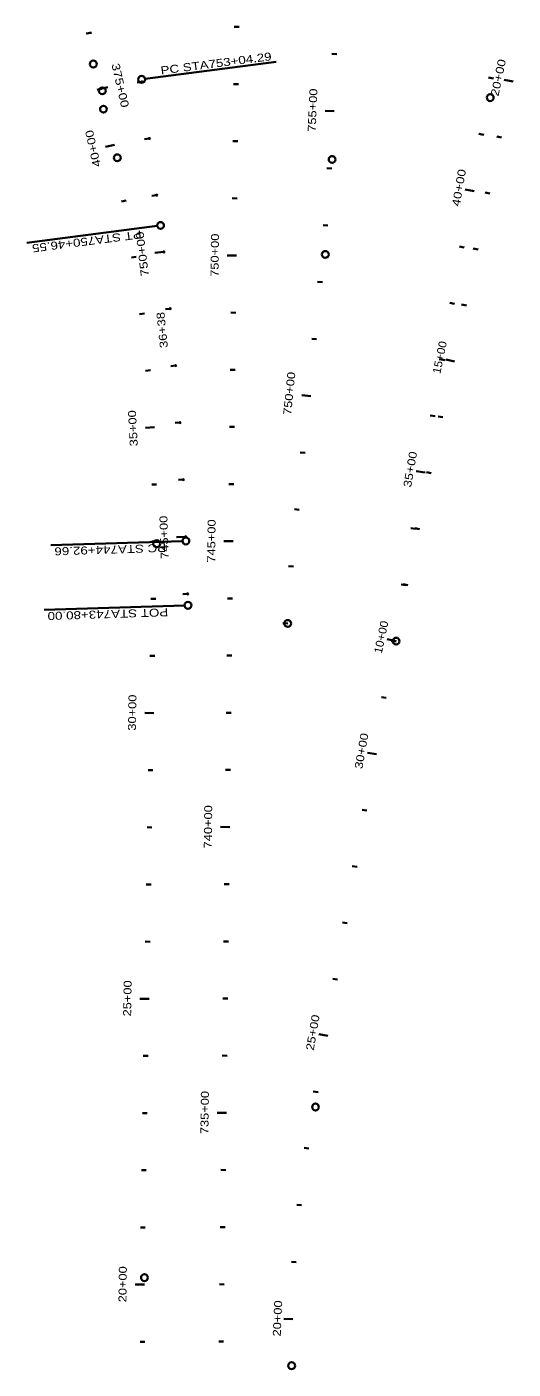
# Model space of a CAD drawing. Extents: x 2357892 to 2370172, y 6966790 to 6985499.
# Drawn here: x 2364100 to 2364952, y 6973878 to 6976226 of the extents above; entities that cross this region are included whole.
import ezdxf
from ezdxf.enums import TextEntityAlignment as Align

# ---------------------------------------------------------------- set-up
doc = ezdxf.new("R2010")
doc.units = 0
doc.header["$LTSCALE"] = 5.6
doc.header["$PDMODE"] = 32
doc.header["$PDSIZE"] = 2.8
doc.layers.add('28', color=7, linetype='Continuous', lineweight=35)
doc.layers.add('7', color=7, linetype='Continuous')

msp = doc.modelspace()

# ---------------------------------------------------------------- linework, layer by layer
at = {"layer": '28'}
for p, q in [((2364212.49, 6976215.881), (2364204.101, 6976214.51)), ((2364205.021, 6976214.781), (2364213.364, 6976216.407)), ((2364471.937, 6976226.218), (2364463.438, 6976226.319)), ((2364307.078, 6976135.201), (2364536.71, 6976164.913)), ((2364642.877, 6976178.521), (2364634.385, 6976178.891)), ((2364917.253, 6976136.182), (2364908.853, 6976137.484)), ((2364231.417, 6976117.689), (2364223.12, 6976115.844)), ((2364226.357, 6976117.089), (2364241.959, 6976120.636)), ((2364301.678, 6976130.177), (2364293.248, 6976129.087)), ((2364470.757, 6976126.225), (2364462.257, 6976126.326)), ((2364952.037, 6976130.422), (2364936.377, 6976133.703)), ((2364638.533, 6976078.616), (2364622.548, 6976079.311)), ((2364253.306, 6976020.114), (2364237.694, 6976016.611)), ((2364314.51, 6976031.004), (2364306.08, 6976029.913)), ((2364469.576, 6976026.232), (2364461.077, 6976026.333)), ((2364900.478, 6976037.601), (2364892.103, 6976039.052)), ((2364931.529, 6976032.548), (2364923.21, 6976034.291)), ((2364634.146, 6975978.712), (2364625.656, 6975979.128)), ((2364327.342, 6975931.831), (2364318.912, 6975930.74)), ((2364468.396, 6975926.239), (2364459.897, 6975926.34)), ((2364883.404, 6975939.069), (2364867.639, 6975941.801)), ((2364911.021, 6975934.673), (2364902.702, 6975936.416)), ((2364274.199, 6975922.32), (2364265.858, 6975920.682)), ((2364627.516, 6975878.937), (2364619.046, 6975879.649)), ((2364328.25, 6975878.048), (2364099.932, 6975848.506)), ((2364339.986, 6975832.634), (2364324.102, 6975830.71)), ((2364866.329, 6975840.538), (2364857.954, 6975841.989)), ((2364890.513, 6975836.799), (2364882.194, 6975838.542)), ((2364291.759, 6975823.874), (2364283.367, 6975822.528)), ((2364467.216, 6975826.246), (2364451.217, 6975826.435)), ((2364617.823, 6975779.41), (2364609.367, 6975780.272)), ((2364849.255, 6975742.006), (2364840.879, 6975743.457)), ((2364870.005, 6975738.924), (2364861.686, 6975740.667)), ((2364305.873, 6975724.875), (2364297.439, 6975723.823)), ((2364351.145, 6975733.26), (2364342.69, 6975732.385)), ((2364466.035, 6975726.253), (2364457.536, 6975726.354)), ((2364607.679, 6975679.926), (2364599.223, 6975680.788)), ((2364832.18, 6975643.475), (2364823.805, 6975644.926)), ((2364849.497, 6975641.05), (2364833.837, 6975644.331)), ((2364316.524, 6975625.444), (2364308.058, 6975624.687)), ((2364360.568, 6975633.706), (2364352.099, 6975632.979)), ((2364464.855, 6975626.26), (2364456.356, 6975626.361)), ((2364597.534, 6975580.441), (2364581.617, 6975582.065)), ((2364368.252, 6975534.003), (2364359.772, 6975533.424)), ((2364463.675, 6975526.267), (2364455.175, 6975526.368)), ((2364815.105, 6975544.943), (2364806.73, 6975546.394)), ((2364828.989, 6975543.175), (2364820.67, 6975544.918)), ((2364323.697, 6975525.702), (2364307.721, 6975524.833)), ((2364587.39, 6975480.957), (2364578.934, 6975481.82)), ((2364374.195, 6975434.181), (2364365.706, 6975433.75)), ((2364798.031, 6975446.412), (2364782.266, 6975449.144)), ((2364808.481, 6975445.301), (2364800.162, 6975447.044)), ((2364327.385, 6975425.77), (2364318.887, 6975425.605)), ((2364462.494, 6975426.274), (2364453.995, 6975426.374)), ((2364577.245, 6975381.473), (2364568.789, 6975382.336)), ((2364780.956, 6975347.88), (2364772.581, 6975349.331)), ((2364787.973, 6975347.426), (2364779.654, 6975349.169)), ((2364372.637, 6975326.745), (2364141.762, 6975319.354)), ((2364327.583, 6975325.77), (2364319.084, 6975325.902)), ((2364378.395, 6975334.27), (2364362.403, 6975333.738)), ((2364461.314, 6975326.281), (2364445.315, 6975326.47)), ((2364567.101, 6975281.989), (2364558.644, 6975282.851)), ((2364763.882, 6975249.349), (2364755.506, 6975250.8)), ((2364767.465, 6975249.552), (2364759.146, 6975251.295)), ((2364325.91, 6975225.784), (2364317.411, 6975225.927)), ((2364381.599, 6975234.322), (2364373.103, 6975234.05)), ((2364460.134, 6975226.288), (2364451.634, 6975226.388)), ((2364376.242, 6975214.14), (2364130.382, 6975206.269)), ((2364556.956, 6975182.505), (2364548.5, 6975183.367)), ((2364746.957, 6975151.677), (2364731.297, 6975154.958)), ((2364746.807, 6975150.817), (2364738.432, 6975152.268)), ((2364324.234, 6975125.798), (2364315.735, 6975125.941)), ((2364458.953, 6975126.295), (2364450.454, 6975126.395)), ((2364729.732, 6975052.286), (2364721.357, 6975053.737)), ((2364322.557, 6975025.812), (2364306.56, 6975026.08)), ((2364457.773, 6975026.302), (2364449.274, 6975026.402)), ((2364712.658, 6974953.754), (2364696.893, 6974956.486)), ((2364320.881, 6974925.826), (2364312.382, 6974925.969)), ((2364456.593, 6974926.309), (2364448.093, 6974926.409)), ((2364695.583, 6974855.223), (2364687.208, 6974856.674)), ((2364319.205, 6974825.84), (2364310.706, 6974825.983)), ((2364455.412, 6974826.316), (2364439.414, 6974826.505)), ((2364678.509, 6974756.691), (2364670.133, 6974758.142)), ((2364317.529, 6974725.854), (2364309.03, 6974725.997)), ((2364454.232, 6974726.323), (2364445.733, 6974726.423)), ((2364661.434, 6974658.16), (2364653.059, 6974659.611)), ((2364315.853, 6974625.868), (2364307.354, 6974626.011)), ((2364453.052, 6974626.33), (2364444.552, 6974626.43)), ((2364644.359, 6974559.628), (2364635.984, 6974561.079)), ((2364314.177, 6974525.882), (2364298.179, 6974526.151)), ((2364451.872, 6974526.337), (2364443.372, 6974526.437)), ((2364627.285, 6974461.097), (2364611.52, 6974463.828)), ((2364312.501, 6974425.896), (2364304.002, 6974426.039)), ((2364450.691, 6974426.344), (2364442.192, 6974426.444)), ((2364610.21, 6974362.565), (2364601.835, 6974364.016)), ((2364310.824, 6974325.91), (2364302.326, 6974326.053)), ((2364449.511, 6974326.351), (2364433.512, 6974326.54)), ((2364594.067, 6974263.88), (2364585.657, 6974265.116)), ((2364309.148, 6974225.925), (2364300.649, 6974226.067)), ((2364448.331, 6974226.358), (2364439.831, 6974226.458)), ((2364581.256, 6974164.709), (2364572.809, 6974165.651)), ((2364307.472, 6974125.939), (2364298.973, 6974126.081)), ((2364447.15, 6974126.365), (2364438.651, 6974126.465)), ((2364571.915, 6974065.152), (2364563.439, 6974065.798)), ((2364305.829, 6974025.949), (2364289.83, 6974026.131)), ((2364445.97, 6974026.372), (2364437.47, 6974026.472)), ((2364566.053, 6973965.329), (2364550.067, 6973965.988)), ((2364306.868, 6973925.954), (2364298.373, 6973925.68)), ((2364444.79, 6973926.379), (2364436.29, 6973926.479))]:
    msp.add_line(p, q, dxfattribs=at)
for centre in [(2364216.334, 6976161.176), (2364301.127, 6976134.431), (2364232.156, 6976114.382), (2364911.733, 6976102.547), (2364234.264, 6976082.306), (2364258.432, 6975997.267), (2364634.866, 6975994.298), (2364334.201, 6975878.818), (2364622.792, 6975828.132), (2364327.524, 6975322.079), (2364378.634, 6975326.937), (2364382.239, 6975214.332), (2364556.956, 6975182.505), (2364746.957, 6975151.677), (2364605.692, 6974336.49), (2364306.001, 6974038.189), (2364563.857, 6973883.997)]:
    msp.add_circle(centre, 6, dxfattribs=at)
at = {"layer": '7'}
for p in [(2364301.678, 6976130.177), (2364314.51, 6976031.004), (2364327.342, 6975931.831), (2364339.986, 6975832.634), (2364351.145, 6975733.26), (2364360.568, 6975633.706), (2364368.252, 6975534.003), (2364374.195, 6975434.181), (2364378.395, 6975334.27), (2364381.599, 6975234.322)]:
    msp.add_point(p, dxfattribs=at)

# ---------------------------------------------------------------- texts
at = {"layer": '28'}
for s, rotation, width, p in [('375+00', 282.808, 1.25, (2364256.938, 6976122.408)), ('20+00', 78.166, 1.25, (2364932.764, 6976135.96)), ('755+00', 87.51, 1.2, (2364607.576, 6976080.267)), ('40+00', 102.646, 1.25, (2364222.714, 6976014.86)), ('40+00', 80.169, 1.25, (2364863.904, 6975943.679)), ('750+00', 96.907, 1.25, (2364309.109, 6975829.748)), ('750+00', 89.324, 1.2, (2364436.219, 6975826.695)), ('15+00', 78.166, 1.1, (2364830.223, 6975646.586)), ('750+00', 84.178, 1.2, (2364566.766, 6975584.296)), ('35+00', 93.114, 1.2, (2364292.723, 6975524.398)), ('35+00', 80.169, 1.2, (2364778.531, 6975451.021)), ('745+00', 91.907, 1.2, (2364347.404, 6975333.472)), ('745+00', 89.324, 1.2, (2364430.318, 6975326.73)), ('10+00', 78.166, 1.1, (2364727.683, 6975157.214)), ('30+00', 89.04, 1.2, (2364291.564, 6975026.45)), ('30+00', 80.169, 1.2, (2364693.159, 6974958.365)), ('740+00', 89.324, 1.2, (2364424.416, 6974826.765)), ('25+00', 89.04, 1.2, (2364283.183, 6974526.519)), ('25+00', 80.169, 1.2, (2364607.786, 6974465.707)), ('735+00', 89.324, 1.2, (2364418.514, 6974326.799)), ('20+00', 89.346, 1.2, (2364274.832, 6974026.384)), ('20+00', 87.64, 1.2, (2364546.082, 6973966.441))]:
    msp.add_text(s, height=14, rotation=rotation, dxfattribs=dict(at, width=width)).set_placement(p, align=Align.CENTER)
for s, rotation, width, p in [('PC STA753+04.29', 7.372, 1.25, (2364335.325, 6976142.889)), ('PT STA750+46.55', 187.372, 1.25, (2364300.003, 6975870.36)), ('36+38', 95.843, 1.2, (2364347.18, 6975665.219)), ('PC STA744+92.66', 181.834, 1.25, (2364343.78, 6975321.819)), ('POT STA743+80.00', 181.834, 1.25, (2364347.385, 6975209.214))]:
    msp.add_text(s, height=14, rotation=rotation, dxfattribs=dict(at, width=width)).set_placement(p)

doc.saveas('drawing.dxf')
